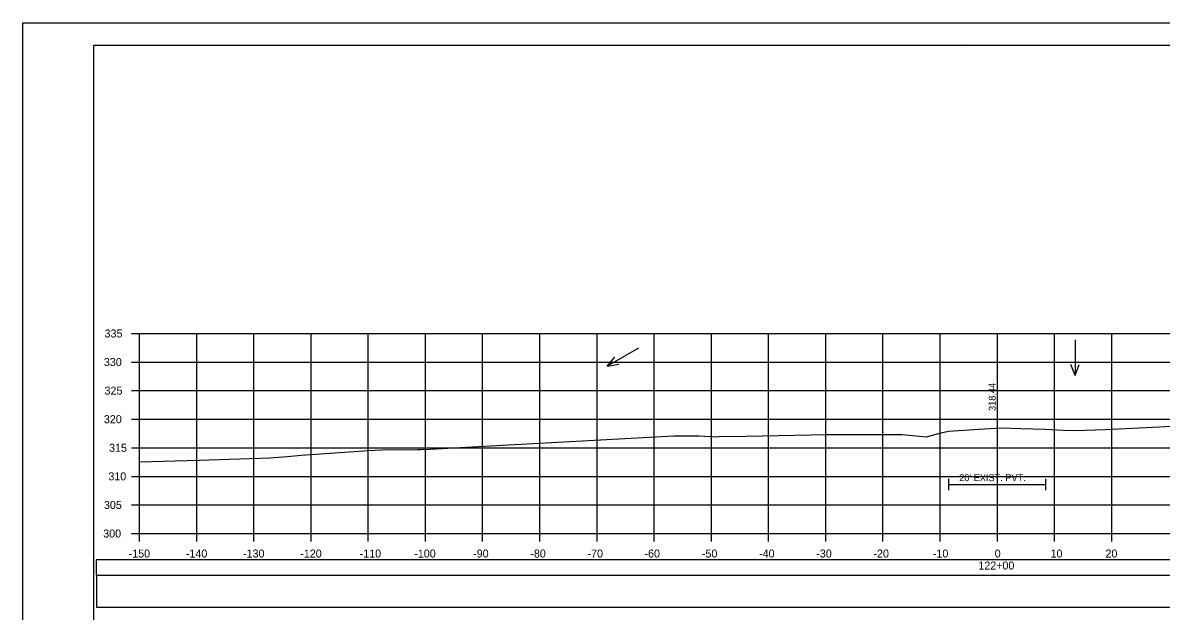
# Model space of a CAD drawing. Extents: x 1370538 to 1372872, y 376220 to 381127.
# Drawn here: x 1371871.6 to 1372070.6, y 380582.1 to 380685.1 of the extents above; entities that cross this region are included whole.
import ezdxf

# ---------------------------------------------------------------- set-up
doc = ezdxf.new("R2010")
doc.units = 0
for name, color, linetype in [('R_Border', 7, 'Continuous'), ('R_Border Notes', 7, 'Continuous'), ('R_Border PE', 7, 'Continuous'), ('R_Border Prem', 7, 'Continuous'), ('R_Dimension', 7, 'Continuous'), ('R_Fin Surface', 7, 'Continuous'), ('R_Grid', 7, 'Continuous'), ('R_No Plot', 7, 'Continuous'), ('R_Water', 7, 'Continuous'), ('R_Water Annot', 7, 'Continuous'), ('R_Xsect Elev', 7, 'Continuous'), ('T_Detection Zones', 7, 'Continuous')]:
    doc.layers.add(name, color=color, linetype=linetype)

msp = doc.modelspace()

# ---------------------------------------------------------------- linework, layer by layer
at = {"layer": 'R_Border'}
for p, q in [((1372033.42, 380605.27), (1372033.42, 380603.27)), ((1372050.37, 380605.27), (1372050.37, 380603.27)), ((1372033.42, 380604.27), (1372050.37, 380604.27))]:
    msp.add_line(p, q, dxfattribs=at)
at = {"layer": 'R_Border Notes'}
for p, q in [((1371883.97, 380681.17), (1372200.15, 380681.17)), ((1371883.97, 380475.71), (1371883.97, 380681.17)), ((1372036.49, 380680.91), (1372036.49, 380680.91)), ((1372036.49, 380680.91), (1372036.49, 380680.91))]:
    msp.add_line(p, q, dxfattribs=at)
at = {"layer": 'R_Border Prem'}
for p, q in [((1371890.57, 380630.71), (1371891.97, 380630.71)), ((1371891.97, 380595.71), (1371891.97, 380630.71)), ((1371890.57, 380625.71), (1371891.97, 380625.71)), ((1371890.57, 380620.71), (1371891.97, 380620.71)), ((1371890.57, 380615.71), (1371891.97, 380615.71)), ((1371890.57, 380610.71), (1371891.97, 380610.71)), ((1371890.57, 380605.71), (1371891.97, 380605.71)), ((1371890.57, 380600.71), (1371891.97, 380600.71)), ((1371890.57, 380595.71), (1371891.97, 380595.71)), ((1371891.97, 380595.71), (1372191.97, 380595.71)), ((1371891.97, 380594.31), (1371891.97, 380595.71)), ((1371901.97, 380594.31), (1371901.97, 380595.71)), ((1371911.97, 380594.31), (1371911.97, 380595.71)), ((1371921.97, 380594.31), (1371921.97, 380595.71)), ((1371931.97, 380594.31), (1371931.97, 380595.71)), ((1371941.97, 380594.31), (1371941.97, 380595.71)), ((1371951.97, 380594.31), (1371951.97, 380595.71)), ((1371961.97, 380594.31), (1371961.97, 380595.71)), ((1371971.97, 380594.31), (1371971.97, 380595.71)), ((1371981.97, 380594.31), (1371981.97, 380595.71)), ((1371991.97, 380594.31), (1371991.97, 380595.71)), ((1372001.97, 380594.31), (1372001.97, 380595.71)), ((1372011.97, 380594.31), (1372011.97, 380595.71)), ((1372021.97, 380594.31), (1372021.97, 380595.71)), ((1372031.97, 380594.31), (1372031.97, 380595.71)), ((1372041.97, 380594.31), (1372041.97, 380595.71)), ((1372051.97, 380594.31), (1372051.97, 380595.71)), ((1372061.97, 380594.31), (1372061.97, 380595.71))]:
    msp.add_line(p, q, dxfattribs=at)
at = {"layer": 'R_Dimension'}
msp.add_lwpolyline([(1371891.97, 380608.26), (1371902.42, 380608.57), (1371914.75, 380608.96), (1371917.85, 380609.2), (1371920.26, 380609.42), (1371931.99, 380610.21), (1371934.35, 380610.33), (1371940.56, 380610.41), (1371941.13, 380610.41), (1371942.8, 380610.46), (1371955.47, 380611.16), (1371985.39, 380612.82), (1371989.67, 380612.79), (1371989.85, 380612.79), (1371989.86, 380612.79), (1371992.78, 380612.65), (1371993.13, 380612.66), (1371998.05, 380612.76), (1372012.1, 380613.02), (1372013.51, 380613.02), (1372025.32, 380613.04), (1372025.95, 380612.99), (1372029.61, 380612.65), (1372031.89, 380613.24), (1372033.42, 380613.61), (1372038.75, 380613.97), (1372042.64, 380614.19), (1372046.1, 380614.07), (1372050.37, 380613.95), (1372053.48, 380613.82), (1372055.55, 380613.75), (1372060.83, 380613.93), (1372065.61, 380614.17), (1372088.82, 380615.31)], dxfattribs=at)
at = {"layer": 'R_Fin Surface'}
msp.add_lwpolyline([(1371884.44, 380582.8), (1372199.45, 380582.8), (1372199.45, 380588.37), (1371884.44, 380588.37)], close=True, dxfattribs=at)
at = {"layer": 'R_Grid'}
for p, q in [((1371891.97, 380630.71), (1372191.97, 380630.71)), ((1371891.97, 380595.71), (1371891.97, 380630.71)), ((1371901.97, 380595.71), (1371901.97, 380630.71)), ((1371911.97, 380595.71), (1371911.97, 380630.71)), ((1371921.97, 380595.71), (1371921.97, 380630.71)), ((1371931.97, 380595.71), (1371931.97, 380630.71)), ((1371941.97, 380595.71), (1371941.97, 380630.71)), ((1371951.97, 380595.71), (1371951.97, 380630.71)), ((1371961.97, 380595.71), (1371961.97, 380630.71)), ((1371971.97, 380595.71), (1371971.97, 380630.71)), ((1371981.97, 380595.71), (1371981.97, 380630.71)), ((1371991.97, 380595.71), (1371991.97, 380630.71)), ((1372001.97, 380595.71), (1372001.97, 380630.71)), ((1372011.97, 380595.71), (1372011.97, 380630.71)), ((1372021.97, 380595.71), (1372021.97, 380630.71)), ((1372031.97, 380595.71), (1372031.97, 380630.71)), ((1372041.97, 380595.71), (1372041.97, 380630.71)), ((1372051.97, 380595.71), (1372051.97, 380630.71)), ((1372061.97, 380595.71), (1372061.97, 380630.71)), ((1371891.97, 380625.71), (1372191.97, 380625.71)), ((1371891.97, 380620.71), (1372191.97, 380620.71)), ((1371891.97, 380615.71), (1372191.97, 380615.71)), ((1371891.97, 380610.71), (1372191.97, 380610.71)), ((1371891.97, 380605.71), (1372191.97, 380605.71)), ((1371891.97, 380600.71), (1372191.97, 380600.71)), ((1371891.97, 380595.71), (1372191.97, 380595.71))]:
    msp.add_line(p, q, dxfattribs=at)
at = {"layer": 'R_No Plot'}
msp.add_line((1371871.57, 380685.06), (1372204.9, 380685.06), dxfattribs=at)
for points in [[(1371871.56, 380685.06), (1372204.9, 380685.06), (1372204.9, 380471.72), (1371871.56, 380471.72)], [(1372117.89, 380681.17), (1372117.89, 380671.29), (1372153.62, 380671.29), (1372153.62, 380668.37), (1372176.82, 380668.37), (1372176.82, 380644.03), (1372200.15, 380644.03), (1372200.15, 380475.71), (1371883.97, 380475.71), (1371883.97, 380681.17)]]:
    msp.add_lwpolyline(points, close=True, dxfattribs=at)
at = {"layer": 'R_Water Annot'}
for p, q in [((1372055.55, 380629.61), (1372055.55, 380623.33)), ((1371979.2, 380628.14), (1371973.76, 380624.99)), ((1371973.76, 380624.99), (1371975.07, 380626.56)), ((1371973.76, 380624.99), (1371975.78, 380625.35)), ((1372055.55, 380623.33), (1372054.85, 380625.25)), ((1372055.55, 380623.33), (1372056.25, 380625.25))]:
    msp.add_line(p, q, dxfattribs=at)
at = {"layer": 'R_Xsect Elev'}
msp.add_line((1372041.97, 380614.15), (1372041.97, 380624.15), dxfattribs=at)
at = {"layer": 'T_Detection Zones'}
msp.add_lwpolyline([(1371884.38, 380588.43), (1372199.5, 380588.43), (1372199.5, 380591.13), (1371884.38, 380591.13)], close=True, dxfattribs=at)

# ---------------------------------------------------------------- texts
at = {"layer": 'R_Border PE'}
for s, p in [('335', (1371885.86, 380630.01)), ('330', (1371885.74, 380625.01)), ('325', (1371885.86, 380620.01)), ('320', (1371885.74, 380615.01)), ('315', (1371886.65, 380610.01)), ('310', (1371886.53, 380605.01)), ('305', (1371885.75, 380600.01)), ('300', (1371885.63, 380595.01)), ('-150', (1371890.08, 380591.51)), ('-140', (1371900.08, 380591.51)), ('-130', (1371910.08, 380591.51)), ('-120', (1371920.08, 380591.51)), ('-110', (1371930.47, 380591.51)), ('-100', (1371940.02, 380591.51)), ('-90', (1371950.31, 380591.51)), ('-80', (1371960.31, 380591.51)), ('-70', (1371970.31, 380591.51)), ('-60', (1371980.27, 380591.51)), ('-50', (1371990.31, 380591.51)), ('-40', (1372000.31, 380591.51)), ('-30', (1372010.31, 380591.51)), ('-20', (1372020.31, 380591.51)), ('-10', (1372030.7, 380591.51)), ('0', (1372041.51, 380591.51)), ('10', (1372051.28, 380591.51)), ('20', (1372060.88, 380591.51)), ('122+00', (1372038.65, 380589.41))]:
    msp.add_text(s, height=1.4, dxfattribs=at).set_placement(p)
at = {"layer": 'R_Water'}
msp.add_text("20' EXIST. PVT.", height=1.2, dxfattribs=at).set_placement((1372035.3, 380604.87))
at = {"layer": 'R_Xsect Elev'}
msp.add_text('318.44', height=1.2, rotation=90, dxfattribs=at).set_placement((1372041.67, 380617.15))

doc.saveas('drawing.dxf')
